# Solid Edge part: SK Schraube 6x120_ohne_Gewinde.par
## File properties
Author: fknapp
Template: Normal.par
Last saved by: fknapp
Revision: 21
Application: Solid Edge
Genauigkeit: 0,99
Username: fknapp
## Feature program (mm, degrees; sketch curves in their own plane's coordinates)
sketch for "unnamed RevolvedProtrusion 1" plane through (0, 0, 0) normal (0, 0, 1) x-axis (1, 0, 0)
  line (0, 120) -> (5.5, 120)
  line (5.5, 120) -> (5.5, 119)
  line (5.5, 119) -> (3, 116.5)
  line (3, 116.5) -> (3, 6)
  line (3, 6) -> (0.2, 0)
  line (0.2, 0) -> (0, 0)
  line (0, 120) -> (0, 0)
revolve "unnamed RevolvedProtrusion 1" add full turn 360 deg
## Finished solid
Body 1: solid body, 6 faces, 5 edges, 0 vertices.
  Faces by surface: cone 2, cylinder 2, plane 2
  Edges by curve: circle 5
Bounding box of the edges (mm): 11.000 x 120.000 x 11.000, from (-5.5, 0, -5.5) to (5.5, 120, 5.5).
Cylindrical faces by radius (mm): R3 x1, R5.5 x1
Conical faces (half-angle, radius in mm at the cone's reference point): 25.0169 deg R3 x1, 45 deg R5.5 x1
Planar faces by outward normal: +y 1, -y 1
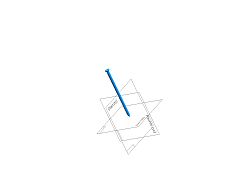
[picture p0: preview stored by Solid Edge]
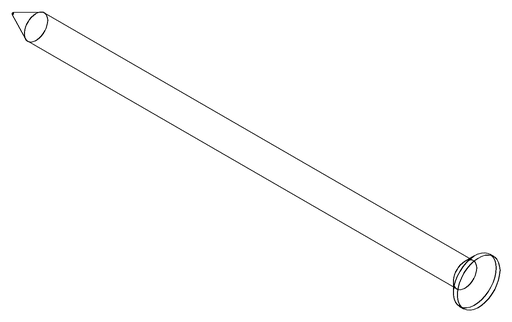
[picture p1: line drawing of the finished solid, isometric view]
